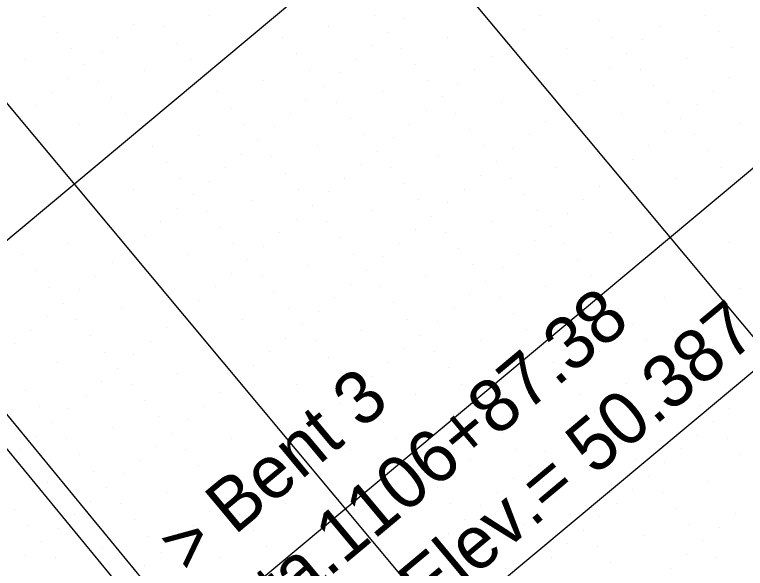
# Model space of a CAD drawing. Extents: x 2042995 to 2043795, y 305365 to 306249.
# Drawn here: x 2043376.43 to 2043410.97, y 305730.9 to 305757.07 of the extents above; entities that cross this region are included whole.
import ezdxf

# ---------------------------------------------------------------- set-up
doc = ezdxf.new("R2010")
doc.units = 0
for name, color, linetype in [('BR_CENTER LINES', 7, 'Continuous'), ('BR_CONCRETE', 7, 'Continuous'), ('BR_GRID DOTS', 7, 'Continuous'), ('BR_GRID LINES', 7, 'Continuous'), ('BR_PRESTRESSED BEAM', 7, 'Continuous'), ('BR_TEXT', 7, 'Continuous')]:
    doc.layers.add(name, color=color, linetype=linetype)

msp = doc.modelspace()

# ---------------------------------------------------------------- linework, layer by layer
at = {"layer": 'BR_CENTER LINES'}
msp.add_line((2043427.985, 305754.114), (2043332.14, 305674.065), dxfattribs=at)
at = {"layer": 'BR_CONCRETE'}
for points in [[(2043139.109, 306017.548), (2043148.199, 306007.16), (2043160.233, 305993.368), (2043172.245, 305979.557), (2043184.234, 305965.727), (2043196.201, 305951.879), (2043208.145, 305938.012), (2043220.067, 305924.126), (2043231.966, 305910.221), (2043243.843, 305896.297), (2043255.698, 305882.355), (2043267.529, 305868.394), (2043279.339, 305854.414), (2043291.126, 305840.415), (2043302.89, 305826.398), (2043314.632, 305812.361), (2043326.352, 305798.306), (2043338.049, 305784.233), (2043349.724, 305770.14), (2043361.376, 305756.029), (2043373.005, 305741.899), (2043384.613, 305727.75), (2043396.197, 305713.582), (2043407.76, 305699.396), (2043419.299, 305685.191), (2043430.817, 305670.967), (2043442.311, 305656.724), (2043453.784, 305642.463), (2043465.234, 305628.182), (2043476.661, 305613.883), (2043488.066, 305599.566), (2043499.448, 305585.229), (2043510.808, 305570.874), (2043522.146, 305556.5), (2043533.461, 305542.107), (2043544.753, 305527.695), (2043547.219, 305524.543)], [(2043273.14, 305860.139), (2043278.86, 305853.362), (2043290.647, 305839.364), (2043302.411, 305825.346), (2043314.153, 305811.31), (2043325.873, 305797.255), (2043337.57, 305783.181), (2043349.245, 305769.089), (2043360.897, 305754.977), (2043372.526, 305740.847), (2043384.134, 305726.698), (2043395.718, 305712.531), (2043407.281, 305698.344), (2043418.82, 305684.139), (2043425.623, 305675.744)]]:
    msp.add_spline(points, degree=3, dxfattribs=at)
at = {"layer": 'BR_GRID DOTS'}
for p, q in [((2043377.824, 305756.998), (2043377.824, 305756.998)), ((2043385.634, 305757.006), (2043385.634, 305757.006)), ((2043393.444, 305757.015), (2043393.444, 305757.015)), ((2043394.853, 305756.888), (2043394.853, 305756.888)), ((2043401.255, 305757.023), (2043401.255, 305757.023)), ((2043409.065, 305757.032), (2043409.065, 305757.032)), ((2043382.05, 305756.618), (2043382.05, 305756.618)), ((2043404.072, 305756.77), (2043404.072, 305756.77)), ((2043378.465, 305756.23), (2043378.465, 305756.23)), ((2043383.458, 305756.492), (2043383.458, 305756.492)), ((2043391.268, 305756.5), (2043391.268, 305756.5)), ((2043394.085, 305756.247), (2043394.085, 305756.247)), ((2043400.487, 305756.382), (2043400.487, 305756.382)), ((2043406.889, 305756.517), (2043406.889, 305756.517)), ((2043409.706, 305756.264), (2043409.706, 305756.264)), ((2043381.282, 305755.977), (2043381.282, 305755.977)), ((2043389.092, 305755.986), (2043389.092, 305755.986)), ((2043396.903, 305755.994), (2043396.903, 305755.994)), ((2043404.713, 305756.003), (2043404.713, 305756.003)), ((2043406.121, 305755.876), (2043406.121, 305755.876)), ((2043384.099, 305755.724), (2043384.099, 305755.724)), ((2043393.318, 305755.606), (2043393.318, 305755.606)), ((2043399.72, 305755.741), (2043399.72, 305755.741)), ((2043379.106, 305755.463), (2043379.106, 305755.463)), ((2043380.515, 305755.336), (2043380.515, 305755.336)), ((2043389.733, 305755.218), (2043389.733, 305755.218)), ((2043394.726, 305755.48), (2043394.726, 305755.48)), ((2043402.537, 305755.488), (2043402.537, 305755.488)), ((2043405.354, 305755.235), (2043405.354, 305755.235)), ((2043410.347, 305755.497), (2043410.347, 305755.497)), ((2043376.93, 305754.948), (2043376.93, 305754.948)), ((2043384.74, 305754.957), (2043384.74, 305754.957)), ((2043392.55, 305754.965), (2043392.55, 305754.965)), ((2043398.952, 305755.1), (2043398.952, 305755.1)), ((2043408.171, 305754.982), (2043408.171, 305754.982)), ((2043379.747, 305754.695), (2043379.747, 305754.695)), ((2043395.367, 305754.712), (2043395.367, 305754.712)), ((2043404.586, 305754.594), (2043404.586, 305754.594)), ((2043405.995, 305754.468), (2043405.995, 305754.468)), ((2043382.564, 305754.442), (2043382.564, 305754.442)), ((2043390.374, 305754.451), (2043390.374, 305754.451)), ((2043391.783, 305754.324), (2043391.783, 305754.324)), ((2043398.185, 305754.459), (2043398.185, 305754.459)), ((2043378.979, 305754.054), (2043378.979, 305754.054)), ((2043380.388, 305753.928), (2043380.388, 305753.928)), ((2043388.198, 305753.936), (2043388.198, 305753.936)), ((2043396.009, 305753.945), (2043396.009, 305753.945)), ((2043397.417, 305753.818), (2043397.417, 305753.818)), ((2043403.819, 305753.953), (2043403.819, 305753.953)), ((2043410.22, 305754.088), (2043410.22, 305754.088)), ((2043391.015, 305753.683), (2043391.015, 305753.683)), ((2043393.832, 305753.43), (2043393.832, 305753.43)), ((2043406.636, 305753.7), (2043406.636, 305753.7)), ((2043409.453, 305753.447), (2043409.453, 305753.447)), ((2043378.212, 305753.413), (2043378.212, 305753.413)), ((2043381.029, 305753.16), (2043381.029, 305753.16)), ((2043386.022, 305753.422), (2043386.022, 305753.422)), ((2043396.65, 305753.177), (2043396.65, 305753.177)), ((2043403.051, 305753.312), (2043403.051, 305753.312)), ((2043377.444, 305752.772), (2043377.444, 305752.772)), ((2043390.248, 305753.042), (2043390.248, 305753.042)), ((2043391.656, 305752.916), (2043391.656, 305752.916)), ((2043399.467, 305752.924), (2043399.467, 305752.924)), ((2043407.277, 305752.933), (2043407.277, 305752.933)), ((2043408.685, 305752.806), (2043408.685, 305752.806)), ((2043386.663, 305752.654), (2043386.663, 305752.654)), ((2043389.48, 305752.401), (2043389.48, 305752.401)), ((2043395.882, 305752.536), (2043395.882, 305752.536)), ((2043397.291, 305752.41), (2043397.291, 305752.41)), ((2043402.284, 305752.671), (2043402.284, 305752.671)), ((2043405.101, 305752.418), (2043405.101, 305752.418)), ((2043376.677, 305752.131), (2043376.677, 305752.131)), ((2043381.67, 305752.393), (2043381.67, 305752.393)), ((2043392.297, 305752.148), (2043392.297, 305752.148)), ((2043407.918, 305752.165), (2043407.918, 305752.165)), ((2043379.494, 305751.878), (2043379.494, 305751.878)), ((2043387.304, 305751.887), (2043387.304, 305751.887)), ((2043388.713, 305751.76), (2043388.713, 305751.76)), ((2043395.114, 305751.895), (2043395.114, 305751.895)), ((2043401.516, 305752.03), (2043401.516, 305752.03)), ((2043410.735, 305751.912), (2043410.735, 305751.912)), ((2043385.128, 305751.372), (2043385.128, 305751.372)), ((2043392.938, 305751.381), (2043392.938, 305751.381)), ((2043397.932, 305751.642), (2043397.932, 305751.642)), ((2043400.749, 305751.389), (2043400.749, 305751.389)), ((2043407.15, 305751.524), (2043407.15, 305751.524)), ((2043408.559, 305751.398), (2043408.559, 305751.398)), ((2043387.945, 305751.119), (2043387.945, 305751.119)), ((2043394.347, 305751.254), (2043394.347, 305751.254)), ((2043382.952, 305750.858), (2043382.952, 305750.858)), ((2043390.762, 305750.866), (2043390.762, 305750.866)), ((2043398.573, 305750.875), (2043398.573, 305750.875)), ((2043399.981, 305750.748), (2043399.981, 305750.748)), ((2043406.383, 305750.883), (2043406.383, 305750.883)), ((2043387.178, 305750.478), (2043387.178, 305750.478)), ((2043388.586, 305750.352), (2043388.586, 305750.352)), ((2043393.579, 305750.613), (2043393.579, 305750.613)), ((2043396.397, 305750.36), (2043396.397, 305750.36)), ((2043409.2, 305750.63), (2043409.2, 305750.63)), ((2043383.593, 305750.09), (2043383.593, 305750.09)), ((2043399.214, 305750.107), (2043399.214, 305750.107)), ((2043405.615, 305750.242), (2043405.615, 305750.242)), ((2043386.41, 305749.837), (2043386.41, 305749.837)), ((2043392.812, 305749.972), (2043392.812, 305749.972)), ((2043394.22, 305749.846), (2043394.22, 305749.846)), ((2043402.031, 305749.854), (2043402.031, 305749.854)), ((2043409.841, 305749.863), (2043409.841, 305749.863)), ((2043384.234, 305749.322), (2043384.234, 305749.322)), ((2043389.227, 305749.584), (2043389.227, 305749.584)), ((2043392.044, 305749.331), (2043392.044, 305749.331)), ((2043398.446, 305749.466), (2043398.446, 305749.466)), ((2043399.855, 305749.34), (2043399.855, 305749.34)), ((2043404.848, 305749.601), (2043404.848, 305749.601)), ((2043407.665, 305749.348), (2043407.665, 305749.348)), ((2043385.643, 305749.196), (2043385.643, 305749.196)), ((2043394.862, 305749.078), (2043394.862, 305749.078)), ((2043404.08, 305748.96), (2043404.08, 305748.96)), ((2043382.058, 305748.808), (2043382.058, 305748.808)), ((2043389.868, 305748.817), (2043389.868, 305748.817)), ((2043391.277, 305748.69), (2043391.277, 305748.69)), ((2043397.679, 305748.825), (2043397.679, 305748.825)), ((2043384.875, 305748.555), (2043384.875, 305748.555)), ((2043387.692, 305748.302), (2043387.692, 305748.302)), ((2043395.503, 305748.311), (2043395.503, 305748.311)), ((2043400.496, 305748.572), (2043400.496, 305748.572)), ((2043403.313, 305748.319), (2043403.313, 305748.319)), ((2043384.108, 305747.914), (2043384.108, 305747.914)), ((2043390.509, 305748.049), (2043390.509, 305748.049)), ((2043396.911, 305748.184), (2043396.911, 305748.184)), ((2043385.516, 305747.787), (2043385.516, 305747.787)), ((2043393.326, 305747.796), (2043393.326, 305747.796)), ((2043401.137, 305747.805), (2043401.137, 305747.805)), ((2043402.545, 305747.678), (2043402.545, 305747.678)), ((2043383.34, 305747.273), (2043383.34, 305747.273)), ((2043389.742, 305747.408), (2043389.742, 305747.408)), ((2043391.15, 305747.281), (2043391.15, 305747.281)), ((2043396.144, 305747.543), (2043396.144, 305747.543)), ((2043398.961, 305747.29), (2043398.961, 305747.29)), ((2043386.157, 305747.02), (2043386.157, 305747.02)), ((2043395.376, 305746.902), (2043395.376, 305746.902)), ((2043401.778, 305747.037), (2043401.778, 305747.037)), ((2043382.573, 305746.632), (2043382.573, 305746.632)), ((2043388.974, 305746.767), (2043388.974, 305746.767)), ((2043396.785, 305746.775), (2043396.785, 305746.775)), ((2043404.595, 305746.784), (2043404.595, 305746.784)), ((2043378.988, 305746.244), (2043378.988, 305746.244)), ((2043386.798, 305746.252), (2043386.798, 305746.252)), ((2043391.791, 305746.514), (2043391.791, 305746.514)), ((2043394.609, 305746.261), (2043394.609, 305746.261)), ((2043401.01, 305746.396), (2043401.01, 305746.396)), ((2043402.419, 305746.27), (2043402.419, 305746.27)), ((2043410.229, 305746.278), (2043410.229, 305746.278)), ((2043381.805, 305745.991), (2043381.805, 305745.991)), ((2043388.207, 305746.126), (2043388.207, 305746.126)), ((2043397.426, 305746.008), (2043397.426, 305746.008)), ((2043376.812, 305745.729), (2043376.812, 305745.729)), ((2043384.622, 305745.738), (2043384.622, 305745.738)), ((2043392.432, 305745.746), (2043392.432, 305745.746)), ((2043393.841, 305745.62), (2043393.841, 305745.62)), ((2043400.243, 305745.755), (2043400.243, 305745.755)), ((2043403.06, 305745.502), (2043403.06, 305745.502)), ((2043381.038, 305745.35), (2043381.038, 305745.35)), ((2043387.439, 305745.485), (2043387.439, 305745.485)), ((2043390.256, 305745.232), (2043390.256, 305745.232)), ((2043398.067, 305745.24), (2043398.067, 305745.24)), ((2043377.453, 305744.962), (2043377.453, 305744.962)), ((2043386.672, 305744.844), (2043386.672, 305744.844)), ((2043393.073, 305744.979), (2043393.073, 305744.979)), ((2043399.475, 305745.114), (2043399.475, 305745.114)), ((2043380.27, 305744.709), (2043380.27, 305744.709)), ((2043388.08, 305744.717), (2043388.08, 305744.717)), ((2043395.891, 305744.726), (2043395.891, 305744.726)), ((2043398.708, 305744.473), (2043398.708, 305744.473)), ((2043403.701, 305744.734), (2043403.701, 305744.734)), ((2043378.094, 305744.194), (2043378.094, 305744.194)), ((2043385.904, 305744.203), (2043385.904, 305744.203)), ((2043392.306, 305744.338), (2043392.306, 305744.338)), ((2043393.715, 305744.211), (2043393.715, 305744.211)), ((2043401.525, 305744.22), (2043401.525, 305744.22)), ((2043379.503, 305744.068), (2043379.503, 305744.068)), ((2043388.721, 305743.95), (2043388.721, 305743.95)), ((2043397.94, 305743.832), (2043397.94, 305743.832)), ((2043410.744, 305744.102), (2043410.744, 305744.102)), ((2043378.735, 305743.427), (2043378.735, 305743.427)), ((2043385.137, 305743.562), (2043385.137, 305743.562)), ((2043391.538, 305743.697), (2043391.538, 305743.697)), ((2043394.356, 305743.444), (2043394.356, 305743.444)), ((2043399.349, 305743.705), (2043399.349, 305743.705)), ((2043407.159, 305743.714), (2043407.159, 305743.714)), ((2043409.976, 305743.461), (2043409.976, 305743.461)), ((2043381.552, 305743.174), (2043381.552, 305743.174)), ((2043389.362, 305743.182), (2043389.362, 305743.182)), ((2043397.173, 305743.191), (2043397.173, 305743.191)), ((2043404.983, 305743.199), (2043404.983, 305743.199)), ((2043377.968, 305742.786), (2043377.968, 305742.786)), ((2043384.369, 305742.921), (2043384.369, 305742.921)), ((2043390.771, 305743.056), (2043390.771, 305743.056)), ((2043399.99, 305742.938), (2043399.99, 305742.938)), ((2043409.209, 305742.82), (2043409.209, 305742.82)), ((2043379.376, 305742.659), (2043379.376, 305742.659)), ((2043387.186, 305742.668), (2043387.186, 305742.668)), ((2043390.003, 305742.415), (2043390.003, 305742.415)), ((2043394.997, 305742.676), (2043394.997, 305742.676)), ((2043396.405, 305742.55), (2043396.405, 305742.55)), ((2043405.624, 305742.432), (2043405.624, 305742.432)), ((2043377.2, 305742.145), (2043377.2, 305742.145)), ((2043383.602, 305742.28), (2043383.602, 305742.28)), ((2043392.821, 305742.162), (2043392.821, 305742.162)), ((2043400.631, 305742.17), (2043400.631, 305742.17)), ((2043408.441, 305742.179), (2043408.441, 305742.179)), ((2043380.017, 305741.892), (2043380.017, 305741.892)), ((2043389.236, 305741.774), (2043389.236, 305741.774)), ((2043395.638, 305741.909), (2043395.638, 305741.909)), ((2043376.432, 305741.504), (2043376.432, 305741.504)), ((2043382.834, 305741.639), (2043382.834, 305741.639)), ((2043390.644, 305741.647), (2043390.644, 305741.647)), ((2043398.455, 305741.656), (2043398.455, 305741.656)), ((2043406.265, 305741.664), (2043406.265, 305741.664)), ((2043407.673, 305741.538), (2043407.673, 305741.538)), ((2043380.658, 305741.124), (2043380.658, 305741.124)), ((2043382.067, 305740.998), (2043382.067, 305740.998)), ((2043388.468, 305741.133), (2043388.468, 305741.133)), ((2043394.87, 305741.268), (2043394.87, 305741.268)), ((2043396.279, 305741.141), (2043396.279, 305741.141)), ((2043404.089, 305741.15), (2043404.089, 305741.15)), ((2043391.285, 305740.88), (2043391.285, 305740.88)), ((2043406.906, 305740.897), (2043406.906, 305740.897)), ((2043378.482, 305740.61), (2043378.482, 305740.61)), ((2043381.299, 305740.357), (2043381.299, 305740.357)), ((2043387.701, 305740.492), (2043387.701, 305740.492)), ((2043394.103, 305740.627), (2043394.103, 305740.627)), ((2043396.92, 305740.374), (2043396.92, 305740.374)), ((2043401.913, 305740.635), (2043401.913, 305740.635)), ((2043409.723, 305740.644), (2043409.723, 305740.644)), ((2043384.116, 305740.104), (2043384.116, 305740.104)), ((2043391.926, 305740.112), (2043391.926, 305740.112)), ((2043393.335, 305739.986), (2043393.335, 305739.986)), ((2043406.138, 305740.256), (2043406.138, 305740.256)), ((2043407.547, 305740.129), (2043407.547, 305740.129)), ((2043380.532, 305739.716), (2043380.532, 305739.716)), ((2043386.933, 305739.851), (2043386.933, 305739.851)), ((2043402.554, 305739.868), (2043402.554, 305739.868)), ((2043405.371, 305739.615), (2043405.371, 305739.615)), ((2043376.947, 305739.328), (2043376.947, 305739.328)), ((2043381.94, 305739.589), (2043381.94, 305739.589)), ((2043389.75, 305739.598), (2043389.75, 305739.598)), ((2043392.568, 305739.345), (2043392.568, 305739.345)), ((2043397.561, 305739.606), (2043397.561, 305739.606)), ((2043408.188, 305739.362), (2043408.188, 305739.362)), ((2043379.764, 305739.075), (2043379.764, 305739.075)), ((2043386.166, 305739.21), (2043386.166, 305739.21)), ((2043395.385, 305739.092), (2043395.385, 305739.092)), ((2043403.195, 305739.1), (2043403.195, 305739.1)), ((2043404.603, 305738.974), (2043404.603, 305738.974)), ((2043382.581, 305738.822), (2043382.581, 305738.822)), ((2043391.8, 305738.704), (2043391.8, 305738.704)), ((2043401.019, 305738.586), (2043401.019, 305738.586)), ((2043408.829, 305738.594), (2043408.829, 305738.594)), ((2043377.588, 305738.56), (2043377.588, 305738.56)), ((2043378.997, 305738.434), (2043378.997, 305738.434)), ((2043385.398, 305738.569), (2043385.398, 305738.569)), ((2043393.209, 305738.577), (2043393.209, 305738.577)), ((2043403.836, 305738.333), (2043403.836, 305738.333)), ((2043410.238, 305738.468), (2043410.238, 305738.468)), ((2043383.222, 305738.054), (2043383.222, 305738.054)), ((2043384.631, 305737.928), (2043384.631, 305737.928)), ((2043391.032, 305738.063), (2043391.032, 305738.063)), ((2043398.843, 305738.071), (2043398.843, 305738.071)), ((2043406.653, 305738.08), (2043406.653, 305738.08)), ((2043378.229, 305737.793), (2043378.229, 305737.793)), ((2043393.85, 305737.81), (2043393.85, 305737.81)), ((2043403.068, 305737.692), (2043403.068, 305737.692)), ((2043404.477, 305737.565), (2043404.477, 305737.565)), ((2043409.47, 305737.827), (2043409.47, 305737.827)), ((2043381.046, 305737.54), (2043381.046, 305737.54)), ((2043383.863, 305737.287), (2043383.863, 305737.287)), ((2043390.265, 305737.422), (2043390.265, 305737.422)), ((2043399.484, 305737.304), (2043399.484, 305737.304)), ((2043377.462, 305737.152), (2043377.462, 305737.152)), ((2043378.87, 305737.025), (2043378.87, 305737.025)), ((2043386.68, 305737.034), (2043386.68, 305737.034)), ((2043394.491, 305737.042), (2043394.491, 305737.042)), ((2043402.301, 305737.051), (2043402.301, 305737.051)), ((2043408.703, 305737.186), (2043408.703, 305737.186)), ((2043410.111, 305737.059), (2043410.111, 305737.059)), ((2043376.694, 305736.511), (2043376.694, 305736.511)), ((2043383.096, 305736.646), (2043383.096, 305736.646)), ((2043384.504, 305736.519), (2043384.504, 305736.519)), ((2043389.497, 305736.781), (2043389.497, 305736.781)), ((2043392.315, 305736.528), (2043392.315, 305736.528)), ((2043400.125, 305736.536), (2043400.125, 305736.536)), ((2043405.118, 305736.798), (2043405.118, 305736.798)), ((2043407.935, 305736.545), (2043407.935, 305736.545)), ((2043379.511, 305736.258), (2043379.511, 305736.258)), ((2043401.533, 305736.41), (2043401.533, 305736.41)), ((2043410.752, 305736.292), (2043410.752, 305736.292)), ((2043382.328, 305736.005), (2043382.328, 305736.005)), ((2043388.73, 305736.14), (2043388.73, 305736.14)), ((2043397.949, 305736.022), (2043397.949, 305736.022)), ((2043405.759, 305736.03), (2043405.759, 305736.03)), ((2043407.167, 305735.904), (2043407.167, 305735.904)), ((2043380.152, 305735.49), (2043380.152, 305735.49)), ((2043385.145, 305735.752), (2043385.145, 305735.752)), ((2043387.962, 305735.499), (2043387.962, 305735.499)), ((2043395.773, 305735.507), (2043395.773, 305735.507)), ((2043400.766, 305735.769), (2043400.766, 305735.769)), ((2043403.583, 305735.516), (2043403.583, 305735.516)), ((2043381.561, 305735.364), (2043381.561, 305735.364)), ((2043399.998, 305735.128), (2043399.998, 305735.128)), ((2043406.4, 305735.263), (2043406.4, 305735.263)), ((2043377.976, 305734.975), (2043377.976, 305734.975)), ((2043385.786, 305734.984), (2043385.786, 305734.984)), ((2043387.195, 305734.858), (2043387.195, 305734.858)), ((2043401.407, 305735.001), (2043401.407, 305735.001)), ((2043409.217, 305735.01), (2043409.217, 305735.01)), ((2043380.793, 305734.722), (2043380.793, 305734.722)), ((2043383.61, 305734.47), (2043383.61, 305734.47)), ((2043396.414, 305734.74), (2043396.414, 305734.74)), ((2043399.231, 305734.487), (2043399.231, 305734.487)), ((2043405.632, 305734.622), (2043405.632, 305734.622)), ((2043407.041, 305734.495), (2043407.041, 305734.495)), ((2043386.427, 305734.217), (2043386.427, 305734.217)), ((2043402.048, 305734.234), (2043402.048, 305734.234)), ((2043380.026, 305734.081), (2043380.026, 305734.081)), ((2043381.434, 305733.955), (2043381.434, 305733.955)), ((2043389.244, 305733.964), (2043389.244, 305733.964)), ((2043397.055, 305733.972), (2043397.055, 305733.972)), ((2043398.463, 305733.846), (2043398.463, 305733.846)), ((2043404.865, 305733.981), (2043404.865, 305733.981)), ((2043376.441, 305733.693), (2043376.441, 305733.693)), ((2043379.258, 305733.44), (2043379.258, 305733.44)), ((2043385.66, 305733.575), (2043385.66, 305733.575)), ((2043387.068, 305733.449), (2043387.068, 305733.449)), ((2043394.879, 305733.458), (2043394.879, 305733.458)), ((2043402.689, 305733.466), (2043402.689, 305733.466)), ((2043407.682, 305733.728), (2043407.682, 305733.728)), ((2043410.499, 305733.475), (2043410.499, 305733.475)), ((2043382.075, 305733.187), (2043382.075, 305733.187)), ((2043397.696, 305733.205), (2043397.696, 305733.205)), ((2043404.097, 305733.34), (2043404.097, 305733.34)), ((2043377.082, 305732.926), (2043377.082, 305732.926)), ((2043378.491, 305732.799), (2043378.491, 305732.799)), ((2043384.892, 305732.934), (2043384.892, 305732.934)), ((2043400.513, 305732.952), (2043400.513, 305732.952)), ((2043408.323, 305732.96), (2043408.323, 305732.96)), ((2043409.732, 305732.834), (2043409.732, 305732.834)), ((2043382.716, 305732.42), (2043382.716, 305732.42)), ((2043387.709, 305732.681), (2043387.709, 305732.681)), ((2043396.928, 305732.564), (2043396.928, 305732.564)), ((2043398.337, 305732.437), (2043398.337, 305732.437)), ((2043403.33, 305732.699), (2043403.33, 305732.699)), ((2043406.147, 305732.446), (2043406.147, 305732.446)), ((2043377.723, 305732.158), (2043377.723, 305732.158)), ((2043384.125, 305732.293), (2043384.125, 305732.293)), ((2043402.562, 305732.058), (2043402.562, 305732.058)), ((2043408.964, 305732.193), (2043408.964, 305732.193)), ((2043380.54, 305731.905), (2043380.54, 305731.905)), ((2043388.35, 305731.914), (2043388.35, 305731.914)), ((2043396.161, 305731.923), (2043396.161, 305731.923)), ((2043403.971, 305731.931), (2043403.971, 305731.931)), ((2043376.956, 305731.517), (2043376.956, 305731.517)), ((2043378.364, 305731.391), (2043378.364, 305731.391)), ((2043383.357, 305731.652), (2043383.357, 305731.652)), ((2043386.174, 305731.399), (2043386.174, 305731.399)), ((2043398.978, 305731.67), (2043398.978, 305731.67)), ((2043401.795, 305731.417), (2043401.795, 305731.417)), ((2043408.197, 305731.552), (2043408.197, 305731.552)), ((2043409.605, 305731.425), (2043409.605, 305731.425)), ((2043382.59, 305731.011), (2043382.59, 305731.011)), ((2043395.393, 305731.282), (2043395.393, 305731.282)), ((2043404.612, 305731.164), (2043404.612, 305731.164)), ((2043399.619, 305730.902), (2043399.619, 305730.902)), ((2043407.429, 305730.911), (2043407.429, 305730.911))]:
    msp.add_line(p, q, dxfattribs=at)
at = {"layer": 'BR_GRID LINES'}
for p, q in [((2043153.138, 306050.98), (2043584.762, 305534.185)), ((2043137.788, 306038.16), (2043569.411, 305521.364)), ((2043425.292, 305787.522), (2043271.788, 305659.317)), ((2043438.113, 305772.172), (2043284.609, 305643.967))]:
    msp.add_line(p, q, dxfattribs=at)
at = {"layer": 'BR_PRESTRESSED BEAM'}
msp.add_spline([(2043269.336, 305856.962), (2043274.734, 305850.568), (2043286.521, 305836.569), (2043298.285, 305822.551), (2043310.027, 305808.515), (2043321.747, 305794.46), (2043333.444, 305780.386), (2043345.119, 305766.294), (2043356.771, 305752.183), (2043368.4, 305738.053), (2043380.007, 305723.904), (2043391.592, 305709.736), (2043403.154, 305695.55), (2043414.694, 305681.345), (2043421.811, 305672.561)], degree=3, dxfattribs=at)

# ---------------------------------------------------------------- texts
at = {"layer": 'BR_TEXT'}
for s, p in [('Sta.1106+87.38', (2043387.417, 305727.226)), ('F.G. Elev.= 50.387', (2043390.221, 305723.869)), ('> Bent 3', (2043384.612, 305730.584))]:
    msp.add_text(s, height=2.5, rotation=39.8684, dxfattribs=at).set_placement(p)

doc.saveas('drawing.dxf')
